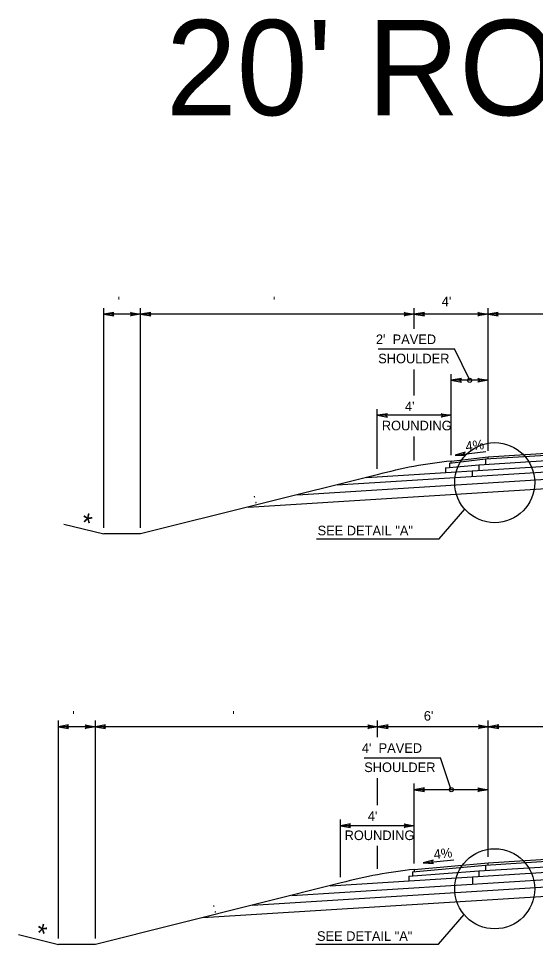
# Model space of a CAD drawing. Extents: x -592 to 1199, y -590 to 416.
# Drawn here: x -425.7 to -350.2, y -200.1 to -65 of the extents above; entities that cross this region are included whole.
import ezdxf

# ---------------------------------------------------------------- set-up
doc = ezdxf.new("R2010")
doc.units = 0
doc.layers.add('1', color=7, linetype='Continuous')
doc.layers.add('Des_ Drain_ Ftrs', color=7, linetype='Continuous')

msp = doc.modelspace()

# ---------------------------------------------------------------- linework, layer by layer
at = {"layer": '1'}
for p, q in [((-413.24, -139.33), (-413.24, -107.26)), ((-407.86, -139.33), (-407.86, -107.26)), ((-367.93, -110.26), (-367.93, -107.26)), ((-357.16, -128.06), (-357.16, -107.26)), ((-407.86, -108.14), (-413.24, -108.14)), ((-367.93, -108.14), (-407.86, -108.14)), ((-357.16, -108.14), (-367.93, -108.14)), ((-330.22, -108.14), (-357.16, -108.14)), ((-373.2, -113.21), (-362.06, -113.21)), ((-359.85, -117.79), (-362.06, -113.21)), ((-367.93, -120.01), (-367.93, -116.22)), ((-362.54, -128.69), (-362.54, -116.91)), ((-357.16, -117.79), (-362.54, -117.79)), ((-373.33, -130.7), (-373.33, -122.02)), ((-362.54, -122.9), (-373.32, -122.9)), ((-367.94, -129.47), (-367.94, -125.97)), ((-361.97, -128.71), (-357.51, -128.18)), ((-357.52, -129.26), (-330.22, -127.54)), ((-357.16, -128.94), (-330.22, -127.24)), ((-374.88, -131.97), (-330.22, -129.16)), ((-362.79, -129.9), (-357.52, -129.26)), ((-362.55, -129.57), (-357.16, -128.94)), ((-362.55, -129.87), (-362.55, -129.57)), ((-358.51, -130.13), (-330.22, -128.35)), ((-357.52, -129.26), (-357.52, -130.07)), ((-357.16, -129.24), (-357.16, -128.94)), ((-379.2, -133.05), (-330.22, -129.97)), ((-363.38, -130.56), (-358.51, -130.13)), ((-363.38, -130.56), (-363.38, -131.25)), ((-362.79, -129.9), (-362.79, -130.51)), ((-359.5, -131), (-359.5, -131.81)), ((-358.51, -130.13), (-358.51, -130.94)), ((-373.33, -131.58), (-407.86, -140.21)), ((-384.97, -134.49), (-330.22, -131.05)), ((-392.17, -136.29), (-330.22, -132.4)), ((-364.29, -140.92), (-360.55, -136.6)), ((-419.07, -138.76), (-413.24, -140.21)), ((-407.86, -140.21), (-413.24, -140.21)), ((-382.22, -140.92), (-364.29, -140.92)), ((-419.85, -199.21), (-419.85, -167.44)), ((-414.46, -199.21), (-414.46, -167.44)), ((-373.32, -169.87), (-373.32, -167.44)), ((-357.16, -187.31), (-357.16, -167.44)), ((-414.46, -168.32), (-419.85, -168.32)), ((-373.23, -168.32), (-414.46, -168.32)), ((-357.07, -168.32), (-373.23, -168.32)), ((-330.12, -168.32), (-357.07, -168.32)), ((-375.23, -172.84), (-364.09, -172.84)), ((-362.54, -177.51), (-364.09, -172.84)), ((-373.32, -179.78), (-373.32, -175.82)), ((-367.93, -188.27), (-367.93, -176.63)), ((-357.16, -177.51), (-367.93, -177.51)), ((-378.71, -190.27), (-378.71, -181.88)), ((-367.93, -182.76), (-378.71, -182.76)), ((-373.32, -189.04), (-373.32, -185.71)), ((-358.49, -189.36), (-330.21, -187.59)), ((-357.52, -188.51), (-330.21, -186.79)), ((-357.16, -188.18), (-330.21, -186.49)), ((-380.2, -191.52), (-330.21, -188.38)), ((-368.17, -189.47), (-357.52, -188.51)), ((-367.93, -189.15), (-357.16, -188.19)), ((-366.64, -188.18), (-362.17, -187.76)), ((-357.52, -188.51), (-357.52, -189.3)), ((-357.16, -188.48), (-357.16, -188.18)), ((-385.82, -192.93), (-330.21, -189.43)), ((-368.73, -190.12), (-358.49, -189.36)), ((-368.73, -190.12), (-368.73, -190.8)), ((-368.17, -189.47), (-368.17, -190.08)), ((-367.93, -189.15), (-367.93, -189.45)), ((-359.46, -190.22), (-359.46, -191.27)), ((-358.49, -189.36), (-358.49, -190.16)), ((-378.58, -191.12), (-414.46, -200.09)), ((-391.55, -194.36), (-330.21, -190.51)), ((-398.78, -196.17), (-330.21, -191.86)), ((-364.39, -200.06), (-360.65, -195.74)), ((-425.68, -198.63), (-419.85, -200.09)), ((-414.46, -200.09), (-419.85, -200.09)), ((-382.32, -200.06), (-364.39, -200.06))]:
    msp.add_line(p, q, dxfattribs=at)
for centre, radius in [((-359.85, -117.79), 0.3), ((-356.19, -132.72), 5.84), ((-362.54, -177.51), 0.3), ((-356.19, -191.97), 5.84)]:
    msp.add_circle(centre, radius, dxfattribs=at)
for centre, end in [((-355.67, -196.41), 105.2381), ((-361.05, -255.98), 105.1262)]:
    msp.add_arc(centre, 67.19, 95.8795, end, dxfattribs=at)
at = {"layer": 'Des_ Drain_ Ftrs'}
for points in [[(-413.24, -108.14), (-411.76, -108.39), (-412.05, -108.14), (-411.76, -107.89)], [(-407.86, -108.14), (-409.34, -108.39), (-409.05, -108.14), (-409.34, -107.89)], [(-407.86, -108.14), (-406.37, -108.39), (-406.66, -108.14), (-406.37, -107.89)], [(-367.93, -108.14), (-369.42, -108.39), (-369.13, -108.14), (-369.42, -107.89)], [(-367.93, -108.14), (-366.44, -108.39), (-366.74, -108.14), (-366.44, -107.89)], [(-357.16, -108.14), (-358.64, -108.39), (-358.35, -108.14), (-358.64, -107.89)], [(-357.16, -108.14), (-355.67, -108.39), (-355.96, -108.14), (-355.67, -107.89)], [(-362.54, -117.79), (-361.06, -118.04), (-361.35, -117.79), (-361.06, -117.54)], [(-357.16, -117.79), (-358.64, -118.04), (-358.35, -117.79), (-358.64, -117.54)], [(-373.32, -122.9), (-371.83, -123.15), (-372.13, -122.9), (-371.83, -122.66)], [(-362.54, -122.9), (-364.03, -123.15), (-363.74, -122.9), (-364.03, -122.66)], [(-361.97, -128.71), (-360.47, -128.78), (-360.79, -128.57), (-360.53, -128.29)], [(-419.85, -168.32), (-418.37, -168.57), (-418.66, -168.32), (-418.37, -168.07)], [(-414.46, -168.32), (-415.95, -168.57), (-415.66, -168.32), (-415.95, -168.07)], [(-414.46, -168.32), (-412.98, -168.57), (-413.27, -168.32), (-412.98, -168.07)], [(-373.23, -168.32), (-374.72, -168.57), (-374.42, -168.32), (-374.72, -168.07)], [(-373.23, -168.32), (-371.74, -168.57), (-372.04, -168.32), (-371.74, -168.07)], [(-357.07, -168.32), (-358.55, -168.57), (-358.26, -168.32), (-358.55, -168.07)], [(-357.07, -168.32), (-355.58, -168.57), (-355.87, -168.32), (-355.58, -168.07)], [(-367.93, -177.51), (-366.44, -177.76), (-366.74, -177.51), (-366.44, -177.26)], [(-357.16, -177.51), (-358.64, -177.76), (-358.35, -177.51), (-358.64, -177.26)], [(-378.71, -182.76), (-377.22, -183.01), (-377.52, -182.76), (-377.22, -182.51)], [(-367.93, -182.76), (-369.42, -183.01), (-369.13, -182.76), (-369.42, -182.51)], [(-366.64, -188.18), (-365.14, -188.29), (-365.46, -188.07), (-365.18, -187.8)]]:
    msp.add_lwpolyline(points, close=True, dxfattribs=at)

# ---------------------------------------------------------------- texts
at = {"layer": '1'}
for s, height, p in [("20' ROADWAY", 13.8979, (-404.17, -79.12)), (" '", 1.4, (-411.75, -106.99)), ("  '", 1.4, (-389.59, -106.99)), ("4'", 1.4, (-363.93, -106.99)), ("2'  PAVED", 1.4, (-373.53, -112.51)), ('SHOULDER', 1.4, (-373.2, -115.31)), ("4'", 1.4, (-369.29, -122.29)), ('ROUNDING', 1.4, (-372.67, -125.09)), ('SEE DETAIL "A"', 1.4, (-382.04, -140.41)), (" '", 1.4, (-418.35, -167.44)), ("  '", 1.4, (-395.54, -167.44)), ("6'", 1.4, (-366.54, -167.44)), ("4'  PAVED", 1.4, (-375.58, -172.14)), ('SHOULDER', 1.4, (-375.24, -174.94)), ("4'", 1.4, (-374.71, -182.06)), ('ROUNDING', 1.4, (-378.1, -184.86)), ('SEE DETAIL "A"', 1.4, (-382.13, -199.56))]:
    msp.add_text(s, height=height, dxfattribs=at).set_placement(p)
for s, height, rotation, p in [('4%', 1.4, 6.9792, (-360.37, -128.14)), (' : ', 1.4, 14.2282, (-391.77, -135.91)), ('*', 2.8, 347.1521, (-416.76, -139.78)), ('4%', 1.4, 5.7657, (-365.03, -187.64)), (' : ', 1.4, 14.2282, (-397.7, -195.62)), ('*', 2.8, 347.1521, (-423.37, -199.66))]:
    msp.add_text(s, height=height, rotation=rotation, dxfattribs=at).set_placement(p)

doc.saveas('drawing.dxf')
